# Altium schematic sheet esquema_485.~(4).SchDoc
size A4
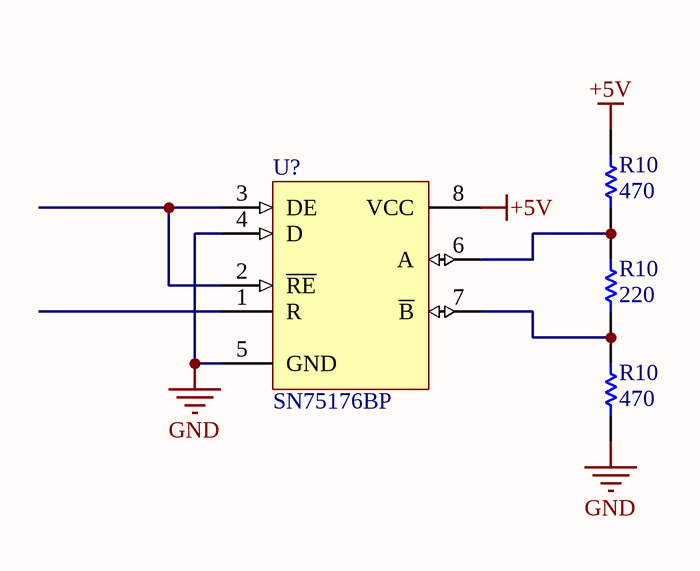
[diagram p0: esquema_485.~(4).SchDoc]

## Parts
(Parts that share a designator on the sheet are numbered #1, #2 ... from top to bottom, then left to right.)
R10#1  value 470  [1005[0402]]  (hidden comment: Carbon 1/8w 5%)
R10#2  value 220  [1005[0402]]  (hidden comment: Carbon 1/8w 5%)
R10#3  value 470  [1005[0402]]  (hidden comment: Carbon 1/8w 5%)
U?  SN75176BP  [P008]

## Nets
+5V: R10#1.2 U?.8(VCC)
GND: R10#3.1 U?.4(D) U?.5(GND)
NetR10#1_1: R10#1.1 R10#2.2 U?.6(A)
NetR10#2_1: R10#2.1 R10#3.2 U?.7(~{B})
NetU?_2: U?.2(~{RE}) U?.3(DE)

Not connected (* = marked no-connect by the designer): U? 1(R)

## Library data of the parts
R10#1-R10#3 = Res Semi: Semiconductor Resistor
U? = SN75176BP: Differential Bus Transceiver; Note: Receiver Hysteresis of 50mV Typical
